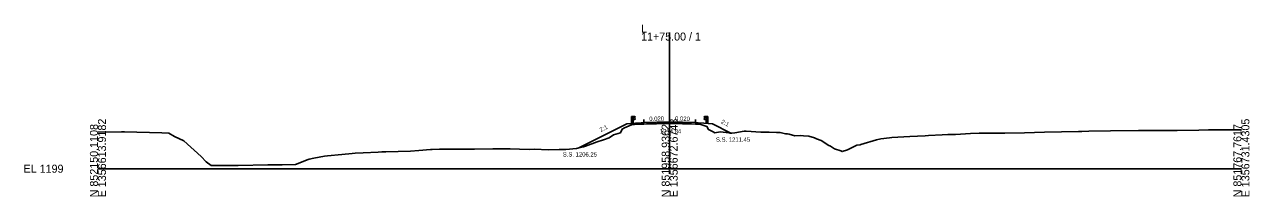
# Model space of a CAD drawing. Extents: x -26 to 4603, y -10 to 4066.
# Drawn here: x 1374.3 to 1802.8, y -9.7 to 50.4 of the extents above; entities that cross this region are included whole.
import ezdxf

# ---------------------------------------------------------------- set-up
doc = ezdxf.new("R2010")
doc.units = 0
for name, color, linetype in [('Exist Cross Section Cell', 7, 'Continuous'), ('Exist XS Center Line Elevation Label', 7, 'Continuous'), ('Exist XS Ground Line', 7, 'Continuous'), ('Prop XS Dump Level', 7, 'Continuous'), ('Prop XS Earthwork Shape', 7, 'Continuous'), ('Prop XS EOT Tick Mark', 7, 'Continuous'), ('Prop XS Finish Grade', 7, 'Continuous'), ('Prop XS Finish Grade Earthwork', 7, 'Continuous'), ('Prop XS Finish Grade Pavement', 7, 'Continuous'), ('Prop XS Guardrail', 7, 'Continuous'), ('Prop XS Pvmt Edge Slope', 7, 'Continuous'), ('Prop XS SE Text', 7, 'Continuous'), ('Prop XS Side Slope Text', 7, 'Continuous'), ('Prop XS SS Elevation Text', 7, 'Continuous'), ('Prop XS Subgrade Earthwork', 7, 'Continuous')]:
    doc.layers.add(name, color=color, linetype=linetype)

msp = doc.modelspace()

# ---------------------------------------------------------------- linework, layer by layer
at = {"layer": 'Exist Cross Section Cell'}
for p, q in [((1600, 0), (1600, 47.56)), ((1400, 0), (1600, 0)), ((1600, 0), (1800, 0))]:
    msp.add_line(p, q, dxfattribs=at)
at = {"layer": 'Exist XS Ground Line'}
msp.add_lwpolyline([(1400, 12.79), (1408.2, 12.91), (1409.29, 12.88), (1422.34, 12.55), (1424.84, 12.44), (1426.81, 11.23), (1430.1, 9.71), (1436.15, 4.28), (1437.86, 2.41), (1439.65, 1.12), (1449.05, 1.13), (1459.39, 1.32), (1464.42, 1.41), (1469.1, 1.48), (1473.55, 3.19), (1473.86, 3.3), (1475.52, 3.65), (1479.28, 4.42), (1480.29, 4.53), (1485.28, 5.02), (1488.9, 5.35), (1490, 5.45), (1492.77, 5.6), (1498.07, 5.8), (1499.32, 5.89), (1500.66, 5.93), (1509.37, 6.14), (1512.26, 6.31), (1516.32, 6.7), (1516.96, 6.73), (1519.47, 6.83), (1521.9, 6.84), (1528.75, 6.82), (1531.75, 6.81), (1538.09, 6.96), (1540.32, 6.98), (1541.95, 6.98), (1544.25, 6.91), (1547.5, 6.87), (1551.09, 6.71), (1552.55, 6.79), (1557.65, 6.57), (1561.39, 6.76), (1563.67, 6.76), (1567.38, 7.02), (1568.71, 7.39), (1569.84, 7.69), (1570.55, 7.91), (1574.68, 9.33), (1576.89, 10.12), (1578.81, 10.77), (1580.35, 11.8), (1582.75, 12.5), (1583.43, 13.86), (1584.24, 14.27), (1586.64, 15.38), (1588.75, 15.57), (1591.89, 15.65), (1595.66, 15.82), (1598.54, 15.85), (1600, 15.84), (1603.94, 15.82), (1606.37, 15.81), (1609.08, 15.6), (1610.93, 15.47), (1613.05, 14.78), (1613.6, 13.67), (1615.19, 12.83), (1615.78, 12.55), (1617.62, 12.85), (1618.77, 12.78), (1620.82, 12.48), (1621.14, 12.44), (1621.73, 12.46), (1622.8, 12.58), (1626.06, 13.11), (1626.73, 13.08), (1631.92, 12.71), (1633.39, 12.74), (1634.81, 12.74), (1637.36, 12.65), (1638.7, 12.63), (1640.5, 12.19), (1641.23, 12.13), (1641.8, 12.01), (1643.78, 11.46), (1645.76, 11.64), (1646.77, 11.49), (1648.65, 11.4), (1650.62, 10.74), (1651.42, 10.41), (1652.96, 9.85), (1653.53, 9.48), (1655.41, 8.25), (1656.25, 7.84), (1657.69, 6.99), (1659.92, 6.19), (1660.3, 5.97), (1662.24, 6.56), (1665.47, 8.17), (1666.61, 8.37), (1666.91, 8.4), (1672.38, 10.07), (1673.83, 10.41), (1676.96, 10.81), (1677.74, 10.94), (1684.04, 11.23), (1689.35, 11.52), (1690.55, 11.63), (1695.29, 11.82), (1697.28, 11.92), (1698.08, 11.94), (1699.08, 11.96), (1699.98, 11.98), (1705.23, 12.27), (1708.28, 12.37), (1710.55, 12.38), (1717.21, 12.43), (1724.17, 12.56), (1731.14, 12.76), (1742.98, 13.03), (1743.67, 13.04), (1744.22, 13.04), (1746.62, 13.1), (1754.21, 13.25), (1764.06, 13.29), (1768.98, 13.29), (1777.52, 13.29), (1785.14, 13.44), (1788.49, 13.54), (1798.67, 13.56), (1800, 13.56)], dxfattribs=at)
at = {"layer": 'Prop XS Dump Level'}
for p, q in [((1600, 16.32), (1591, 16.14)), ((1609, 16.14), (1600, 16.32))]:
    msp.add_line(p, q, dxfattribs=at)
at = {"layer": 'Prop XS Earthwork Shape'}
for points in [[(1590.42, 15.61), (1589.98, 16.05), (1588, 15.9), (1585, 15.66), (1568.18, 7.25), (1568.71, 7.39), (1569.84, 7.69), (1570.55, 7.91), (1574.68, 9.33), (1576.89, 10.12), (1578.81, 10.77), (1580.35, 11.8), (1582.75, 12.5), (1583.43, 13.86), (1584.24, 14.27), (1586.64, 15.38), (1588.75, 15.57)], [(1590.42, 15.61), (1589.98, 16.05), (1588, 15.9), (1585, 15.66), (1568.18, 7.25), (1568.71, 7.39), (1569.84, 7.69), (1570.55, 7.91), (1574.68, 9.33), (1576.89, 10.12), (1578.81, 10.77), (1580.35, 11.8), (1582.75, 12.5), (1583.43, 13.86), (1584.24, 14.27), (1586.64, 15.38), (1588.75, 15.57)], [(1590.42, 15.61), (1591.89, 15.65), (1595.66, 15.82), (1598.54, 15.85), (1600, 15.84), (1603.94, 15.82), (1606.37, 15.81), (1609.08, 15.6), (1609.17, 15.59), (1609, 15.59), (1600, 15.77), (1591, 15.59), (1590.45, 15.58)], [(1590.42, 15.61), (1591.89, 15.65), (1595.66, 15.82), (1598.54, 15.85), (1600, 15.84), (1603.94, 15.82), (1606.37, 15.81), (1609.08, 15.6), (1609.17, 15.59), (1609, 15.59), (1600, 15.77), (1591, 15.59), (1590.45, 15.58)], [(1609.17, 15.59), (1610.93, 15.47), (1613.05, 14.78), (1613.6, 13.67), (1615.19, 12.83), (1615.78, 12.55), (1617.62, 12.85), (1618.77, 12.78), (1620.82, 12.48), (1621.14, 12.44), (1621.41, 12.45), (1615, 15.66), (1612, 15.9), (1610.02, 16.05), (1609.55, 15.58)], [(1609.17, 15.59), (1610.93, 15.47), (1613.05, 14.78), (1613.6, 13.67), (1615.19, 12.83), (1615.78, 12.55), (1617.62, 12.85), (1618.77, 12.78), (1620.82, 12.48), (1621.14, 12.44), (1621.41, 12.45), (1615, 15.66), (1612, 15.9), (1610.02, 16.05), (1609.55, 15.58)]]:
    msp.add_lwpolyline(points, close=True, dxfattribs=at)
at = {"layer": 'Prop XS EOT Tick Mark'}
for p, q in [((1591, 16.14), (1591, 17.14)), ((1609, 16.14), (1609, 17.14))]:
    msp.add_line(p, q, dxfattribs=at)
at = {"layer": 'Prop XS Finish Grade'}
for p, q in [((1591, 16.14), (1589.98, 16.05)), ((1609, 16.14), (1610.02, 16.05))]:
    msp.add_line(p, q, dxfattribs=at)
at = {"layer": 'Prop XS Finish Grade Earthwork'}
for p, q in [((1585, 15.66), (1568.18, 7.25)), ((1588, 15.9), (1585, 15.66)), ((1589.98, 16.05), (1588, 15.9)), ((1610.02, 16.05), (1612, 15.9)), ((1612, 15.9), (1615, 15.66)), ((1615, 15.66), (1621.41, 12.45))]:
    msp.add_line(p, q, dxfattribs=at)
at = {"layer": 'Prop XS Finish Grade Pavement'}
for p, q in [((1591, 16.14), (1600, 16.32)), ((1600, 16.32), (1609, 16.14))]:
    msp.add_line(p, q, dxfattribs=at)
at = {"layer": 'Prop XS Guardrail'}
for p, q in [((1586.68, 18.29), (1587.18, 18.29)), ((1586.68, 15.79), (1586.68, 18.29)), ((1587.18, 18.29), (1587.68, 18.29)), ((1587.18, 18.29), (1587.18, 15.79)), ((1587.68, 17.16), (1587.18, 17.16)), ((1587.68, 18.29), (1587.97, 18.09)), ((1587.97, 17.97), (1587.68, 17.77)), ((1587.68, 17.77), (1587.68, 17.68)), ((1587.68, 17.68), (1587.97, 17.48)), ((1587.97, 17.36), (1587.68, 17.16)), ((1587.97, 18.09), (1588, 18.03)), ((1588, 18.03), (1587.97, 17.97)), ((1587.97, 17.48), (1588, 17.42)), ((1588, 17.42), (1587.97, 17.36)), ((1612.03, 18.09), (1612, 18.03)), ((1612, 18.03), (1612.03, 17.97)), ((1612.03, 17.48), (1612, 17.42)), ((1612, 17.42), (1612.03, 17.36)), ((1612.32, 18.29), (1612.03, 18.09)), ((1612.03, 17.97), (1612.32, 17.77)), ((1612.32, 17.68), (1612.03, 17.48)), ((1612.03, 17.36), (1612.32, 17.16)), ((1612.82, 18.29), (1612.32, 18.29)), ((1612.32, 17.77), (1612.32, 17.68)), ((1612.32, 17.16), (1612.82, 17.16)), ((1613.32, 18.29), (1612.82, 18.29)), ((1612.82, 18.29), (1612.82, 15.79)), ((1613.32, 15.79), (1613.32, 18.29))]:
    msp.add_line(p, q, dxfattribs=at)
at = {"layer": 'Prop XS Pvmt Edge Slope'}
for p, q in [((1591, 16.14), (1590.45, 15.58)), ((1609, 16.14), (1609.55, 15.58))]:
    msp.add_line(p, q, dxfattribs=at)
at = {"layer": 'Prop XS Subgrade Earthwork'}
for p, q in [((1590.45, 15.58), (1589.98, 16.05)), ((1591, 15.59), (1590.45, 15.58)), ((1600, 15.77), (1591, 15.59)), ((1609, 15.59), (1600, 15.77)), ((1609, 15.59), (1609.55, 15.58)), ((1609.55, 15.58), (1610.02, 16.05))]:
    msp.add_line(p, q, dxfattribs=at)

# ---------------------------------------------------------------- texts
at = {"layer": 'Exist Cross Section Cell'}
for s, p in [('11+75.00 / 1', (1590, 44.76)), ('L', (1590, 47.56)), ('EL 1199', (1374, -1.4))]:
    msp.add_text(s, height=2.8, dxfattribs=at).set_placement(p)
for s, p in [('E 1356613.9182', (1402.8, -10)), ('E 1356672.6743', (1602.8, -10)), ('E 1356731.4305', (1802.8, -10)), ('N 852150.1108', (1400, -10)), ('N 851958.9362', (1600, -10)), ('N 851767.7617', (1800, -10))]:
    msp.add_text(s, height=2.8, rotation=90, dxfattribs=at).set_placement(p)
at = {"layer": 'Exist XS Center Line Elevation Label'}
msp.add_text('1214.84', height=1.5, dxfattribs=at).set_placement((1596.56, 12.34))
at = {"layer": 'Prop XS Dump Level'}
for p in [(1588, 15.86), (1612, 15.86)]:
    msp.add_text('Case1', height=0.04, dxfattribs=at).set_placement(p)
at = {"layer": 'Prop XS SE Text'}
for rotation, p in [(1.1458, (1592.88, 16.67)), (358.8542, (1601.88, 16.78))]:
    msp.add_text('0.020', height=1.5, rotation=rotation, dxfattribs=at).set_placement(p)
at = {"layer": 'Prop XS Side Slope Text'}
for rotation, p in [(26.5651, (1575.92, 12.79)), (333.4349, (1617.81, 15.93))]:
    msp.add_text('2:1', height=1.5, rotation=rotation, dxfattribs=at).set_placement(p)
at = {"layer": 'Prop XS SS Elevation Text'}
for s, p in [('S.S. 1211.45', (1616.19, 9.45)), ('S.S. 1206.25', (1562.61, 4.25))]:
    msp.add_text(s, height=1.5, dxfattribs=at).set_placement(p)

doc.saveas('drawing.dxf')
